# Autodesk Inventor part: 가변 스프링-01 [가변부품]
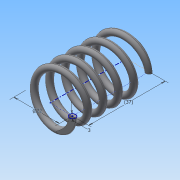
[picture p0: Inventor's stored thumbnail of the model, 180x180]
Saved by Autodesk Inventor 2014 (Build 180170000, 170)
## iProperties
Created: 2015-09
Part Number: 가변 스프링-01 [가변부품]
Material: 강철, 탄소
Document SubType Name: Modeling
Designer: study
Density: 7.87 g/cm^3
Appearance: 반연마
Mass: 18.6318 g
Surface Area: 32.4192 cm^2
Volume: 2.36745 cm^3
Author: study
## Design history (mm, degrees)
sketch "스케치1"
  geometry: L1 (0, 0)-(11, 0); L2 (11, 0)-(11, 25.358); L3 (11, 25.358)-(0, 25.358); L4 (0, 25.358)-(0, 0); C1 r 1.5 at (11, 0)
  constraints: 8 end point, 2 parallel, 1 centre point, 1 coincident, 1 horizontal, 1 perpendicular
  dimensions: "d0" = 25.35829 distance of L1.end L2.end (derived); "d1" = 22 diameter of L2 L4; "d2" = 3 diameter of C1
feature "코일1" sketch "스케치1" pitch "d3" = 10; turns "d5" = 5; dims "d4" = 25.35829 (= d0), "d6" = 0, angle "d7" = 90 deg, angle "d8" = 90 deg, "d9" = 0, "d10" = 0
node "작업 평면1"
sketch "스케치2"
  geometry: L1 (-12.5, 0)-(-9.5, 0) reference; 1 further point
  constraints: 1 horizontal alignment
extrude "돌출1" cut sketch "스케치2" stored distance "d12" = 10; taper "d13" = 0 deg
node "작업 평면2"
sketch "스케치3"
  geometry: L1 (-9.5, 0)-(-12.5, 0) reference; 1 further point
  constraints: 1 horizontal alignment
extrude "돌출2" cut sketch "스케치3" stored distance "d15" = 10; taper "d16" = 0 deg
node "솔리드1"
node "절단 모서리 투영1"
node "절단 모서리 투영2"
other parameters: "d11" = 0, "d14" = 25.35829 (= d0)
